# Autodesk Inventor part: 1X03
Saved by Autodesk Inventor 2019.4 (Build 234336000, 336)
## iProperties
Created: 2020-04
Part Number: 1X03
Material: Generic
Document SubType Name: Modeling
Designer: Administrator
Density: 1 g/cm^3
Appearance: Default
Title: 1X03
Author: Administrator
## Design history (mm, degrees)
feature "Body2"
body "Solid1"
